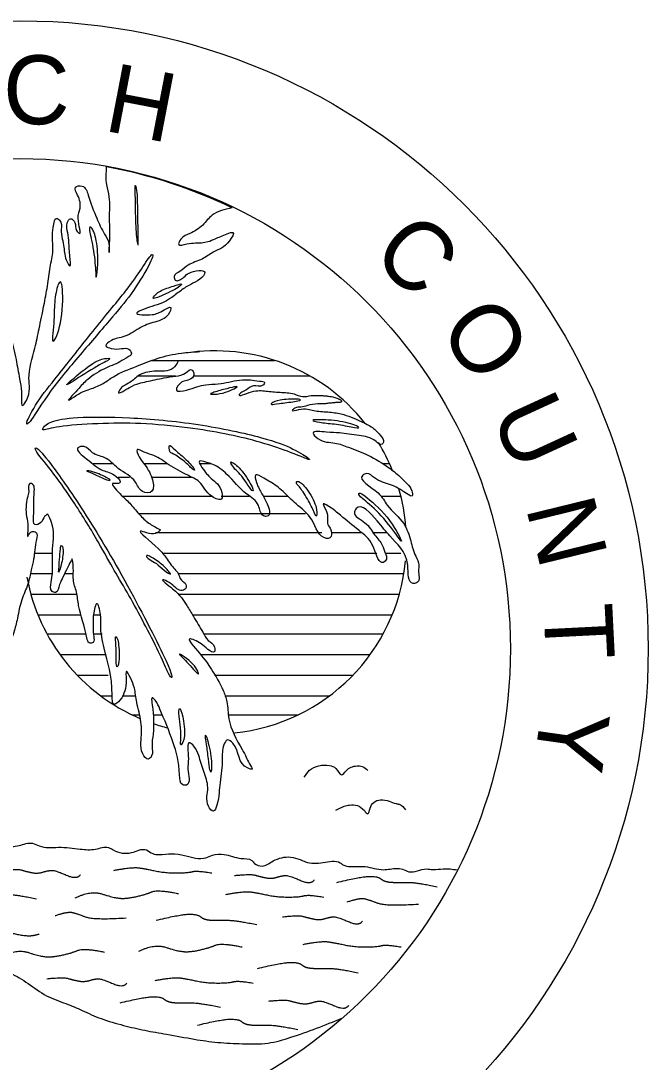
# Model space of a CAD drawing. Extents: x 801329 to 1085229, y 842463 to 1044570.
# Drawn here: x 938507 to 954829, y 915074 to 942158 of the extents above; entities that cross this region are included whole.
import ezdxf

# ---------------------------------------------------------------- set-up
doc = ezdxf.new("R2010")
doc.units = 0
doc.layers.add('Default', color=7, linetype='Continuous')

msp = doc.modelspace()

# ---------------------------------------------------------------- linework, layer by layer
at = {"layer": 'Default'}
for p, q in [((941919, 933328), (945109, 933328)), ((941564, 932925), (942530, 932925)), ((943012, 932925), (946020, 932925)), ((940388, 930643), (940893, 930643)), ((941726, 930643), (942313, 930643)), ((943146, 930643), (943460, 930643)), ((947923, 930643), (948100, 930643)), ((941043, 930286), (941330, 930286)), ((941917, 930286), (942949, 930286)), ((941166, 929793), (943487, 929793)), ((943722, 929793), (944447, 929793)), ((944835, 929793), (945451, 929793)), ((947889, 929793), (948394, 929793)), ((941576, 929346), (945915, 929346)), ((942013, 928854), (946337, 928854)), ((946590, 928854), (947366, 928854)), ((947653, 928854), (948041, 928854)), ((938868, 928317), (939323, 928317)), ((942217, 928317), (947771, 928317)), ((947990, 928317), (948395, 928317)), ((938757, 927780), (939316, 927780)), ((939644, 927780), (939869, 927780)), ((942613, 927780), (948474, 927780)), ((938768, 927243), (939965, 927243)), ((942600, 927243), (948354, 927243)), ((938953, 926706), (940074, 926706)), ((940395, 926706), (940565, 926706)), ((942974, 926706), (948169, 926706)), ((939187, 926214), (940197, 926214)), ((940401, 926214), (940622, 926214)), ((943283, 926214), (947935, 926214)), ((939525, 925678), (940702, 925678)), ((943191, 925678), (947597, 925678)), ((939973, 925141), (940782, 925141)), ((943545, 925141), (947148, 925141)), ((940582, 924604), (940873, 924604)), ((941147, 924604), (941501, 924604)), ((943819, 924604), (946539, 924604)), ((941392, 924112), (941593, 924112)), ((941958, 924112), (942186, 924112)), ((943899, 924112), (945729, 924112))]:
    msp.add_line(p, q, dxfattribs=at)
for radius in [16331, 12746]:
    msp.add_circle((938498, 925828), radius, dxfattribs=at)
for centre, radius, start, end in [((938456, 925819), 12746, 64.2352, 79.6894), ((943561, 928595), 4980, 38.42, 99.1431), ((943561, 928595), 4980, 22.2074, 31.4178), ((943561, 928595), 4980, 4.4987, 16.2458), ((943561, 928595), 4980, 275.8177, 354.498), ((943561, 928595), 4980, 190.4463, 247.1077), ((943561, 928595), 4980, 251.2399, 255.6912)]:
    msp.add_arc(centre, radius, start, end, dxfattribs=at)
for points in [[(934285, 935040), (934093, 935338), (933820, 935630), (933414, 935944), (933247, 936075), (933242, 936183), (933450, 936214), (933843, 936054), (934355, 935907), (934600, 935842), (934845, 935759), (934986, 935682), (935065, 935621), (935214, 935501), (935104, 935694), (934969, 935897), (934823, 936043), (934685, 936156), (934730, 936275), (934860, 936245), (935268, 936013), (935703, 935691), (936012, 935415), (936186, 935234), (936368, 935334), (936274, 935660), (936124, 935909), (936047, 936005), (935946, 936108), (936045, 936174), (936393, 935960), (936788, 935602), (937109, 935261), (937277, 935022), (937508, 934626), (937522, 934957), (937482, 935291), (937360, 935484), (937283, 935637), (937332, 935739), (937505, 935669), (937806, 935144), (938064, 934393), (938238, 933942), (938382, 933347), (938475, 932848), (938522, 932521), (938521, 932302), (938545, 932155), (938651, 932285), (938719, 932858), (938874, 933648), (938982, 934146), (939107, 934752), (939198, 935261), (939270, 935754), (939340, 936180), (939331, 936572), (939363, 936867), (939430, 937016), (939516, 936977), (939559, 936730), (939629, 936270), (939710, 935886), (939783, 935783), (939783, 936049), (939729, 936646), (939715, 936905), (939799, 937010), (939912, 936914), (939958, 936703), (940023, 936632), (939997, 937013), (940047, 937283), (939985, 937628), (939929, 937828), (940101, 937860), (940258, 937628), (940481, 937030), (940684, 936612), (940798, 936365), (940801, 936135), (940822, 936510), (940815, 937042), (940808, 937578), (940743, 937894), (940738, 938360)], [(944004, 937295), (943481, 937100), (943240, 936848), (942905, 936628), (942670, 936481), (942615, 936340), (942823, 936354), (943052, 936382), (943375, 936415), (943560, 936490), (943875, 936616), (944025, 936654), (943938, 936437), (943511, 936140), (943223, 935963), (942862, 935804), (942645, 935642), (942496, 935507), (942526, 935414), (942744, 935489), (942883, 935599), (943295, 935612), (943165, 935441), (942926, 935304), (942666, 935139), (942403, 934941), (942189, 934823), (941914, 934730), (941671, 934644), (941529, 934566), (941924, 934517), (942070, 934555), (942238, 934644), (942406, 934704), (942337, 934516), (942041, 934339), (941641, 934190), (941210, 933954), (941024, 933904), (940863, 933845), (940721, 933702), (940858, 933639), (941128, 933632), (941318, 933617), (941381, 933485), (941303, 933419), (941086, 933290), (940664, 933101), (940202, 932792), (939936, 932512), (939749, 932290), (939952, 932418), (940348, 932593), (940651, 932730), (940915, 932903), (941521, 933174), (942057, 933375), (942683, 933517), (943160, 933556)], [(942600, 933304), (942466, 933122), (941975, 933043), (941560, 932922), (941312, 932732), (941126, 932618), (941045, 932491), (941338, 932624), (941774, 932774), (942229, 932870), (942537, 932918), (942808, 933008), (942951, 933085), (942995, 933021), (943003, 932917), (942825, 932803), (942689, 932758), (942556, 932551), (942821, 932555), (943318, 932695), (943645, 932714), (943920, 932764), (944200, 932815), (944480, 932819), (944713, 932789), (944850, 932748), (944804, 932679), (944564, 932665), (944361, 932554), (944229, 932481), (944190, 932437), (944509, 932506), (944885, 932529), (945252, 932498), (945615, 932453), (945835, 932387), (946064, 932416)], [(946440, 932201), (946232, 932195), (945963, 932152), (945788, 932113), (945637, 932086), (945570, 932024), (945739, 932048), (946134, 932021), (946493, 931986), (946842, 931934), (947361, 931736), (947654, 931578), (947854, 931386), (947942, 931197), (947904, 931146), (947748, 931219), (947308, 931372), (946794, 931440), (946457, 931461), (946112, 931438), (946236, 931292), (946679, 931176), (947032, 931066), (947548, 930857), (948076, 930540), (948374, 930300), (948552, 930122), (948680, 929937), (948689, 929804), (948537, 929867), (948125, 930091), (947710, 930269), (947501, 930385), (947401, 930340), (947801, 929878), (948042, 929561), (948468, 929082), (948650, 928631), (948781, 928233), (948866, 928008), (948854, 927857), (948829, 927558), (948718, 927524), (948572, 928004), (948107, 928760), (947778, 929155), (947232, 929471), (947190, 929388), (947460, 929104), (947715, 928784), (947912, 928520), (947986, 928316), (948017, 928155), (947939, 928074), (947694, 928445), (947355, 928861), (946887, 929243), (946590, 929480), (946373, 929596), (946462, 929396), (946498, 929055), (946572, 928923), (946546, 928710), (946460, 928698), (946077, 929178), (945670, 929594), (945328, 929913), (944998, 930167), (944828, 930262), (944619, 930346), (944636, 930152), (944780, 929855), (944890, 929644), (944964, 929455), (944945, 929282), (944819, 929287), (944690, 929552), (944385, 929850), (943861, 930371), (943503, 930622), (943323, 930680), (943154, 930707), (943220, 930542), (943461, 930258), (943621, 930113), (943735, 929887), (943730, 929725), (943481, 929787), (943150, 930167), (942853, 930339), (942358, 930610)], [(946440, 932201), (946232, 932195), (945963, 932152), (945788, 932113), (945637, 932086), (945570, 932024), (945739, 932048), (946134, 932021), (946493, 931986), (946842, 931934), (947361, 931736), (947654, 931578), (947854, 931386), (947942, 931197), (947904, 931146), (947748, 931219), (947308, 931372), (946794, 931440), (946457, 931461), (946112, 931438), (946236, 931292), (946679, 931176), (947032, 931066), (947548, 930857), (948076, 930540), (948374, 930300), (948552, 930122), (948680, 929937), (948689, 929804), (948537, 929867), (948125, 930091), (947710, 930269), (947501, 930385), (947401, 930340), (947801, 929878), (948042, 929561), (948468, 929082), (948650, 928631), (948781, 928233), (948866, 928008), (948854, 927857), (948829, 927558), (948718, 927524), (948572, 928004), (948107, 928760), (947778, 929155), (947232, 929471), (947190, 929388), (947460, 929104), (947715, 928784), (947912, 928520), (947986, 928316), (948017, 928155), (947939, 928074), (947694, 928445), (947355, 928861), (946887, 929243), (946590, 929480), (946373, 929596), (946462, 929396), (946498, 929055), (946572, 928923), (946546, 928710), (946460, 928698), (946077, 929178), (945670, 929594), (945328, 929913), (944998, 930167), (944828, 930262), (944619, 930346), (944636, 930152), (944780, 929855), (944890, 929644), (944964, 929455), (944945, 929282), (944819, 929287), (944690, 929552), (944385, 929850), (943861, 930371), (943503, 930622), (943323, 930680), (943154, 930707), (943220, 930542), (943461, 930258), (943621, 930113), (943735, 929887), (943730, 929725), (943481, 929787), (943150, 930167), (942853, 930339), (942358, 930610)], [(942358, 930610), (941971, 930849), (941719, 930943), (941535, 931005), (941587, 930815), (941737, 930608), (941932, 930222), (941956, 930047), (941918, 929927), (941671, 929917), (941488, 930162), (941038, 930519), (940676, 930802), (940369, 930924), (940155, 931087), (939994, 931049), (940217, 930767), (940641, 930467), (940991, 930307), (941086, 930146), (940965, 930123), (940907, 930129), (941079, 929865), (941370, 929578), (941618, 929290), (941868, 929074), (942143, 928923)], [(942358, 930610), (941971, 930849), (941719, 930943), (941535, 931005), (941587, 930815), (941737, 930608), (941932, 930222), (941956, 930047), (941918, 929927), (941671, 929917), (941488, 930162), (941038, 930519), (940676, 930802), (940369, 930924), (940155, 931087), (939994, 931049), (940217, 930767), (940641, 930467), (940991, 930307), (941086, 930146), (940965, 930123), (940907, 930129), (941079, 929865), (941370, 929578), (941618, 929290), (941868, 929074), (942143, 928923)], [(939209, 929329), (939127, 929267), (939029, 929111), (938868, 929055), (938840, 929274), (938851, 929828), (938783, 930122), (938743, 930121), (938713, 929919), (938679, 929764), (938657, 929267), (938693, 928977), (938689, 928746), (938766, 928862), (938906, 928850), (938912, 928670), (938840, 928159), (938779, 927877), (938690, 927509), (938531, 927100), (938418, 926620), (938323, 926248), (938177, 925869), (937979, 925323), (937859, 924925), (937680, 924322), (937506, 923867), (937264, 923450), (937039, 923054), (936856, 922786), (936799, 922497), (936733, 922338), (936221, 921903), (935730, 921299), (935295, 920797), (935029, 920527), (934728, 920239), (934600, 919899), (934443, 919515), (934391, 919122), (934430, 918839), (933627, 919026), (933318, 919072), (932919, 919138), (932567, 919166), (932358, 919185), (932337, 919197)], [(939845, 928165), (939726, 927948), (939603, 927687), (939516, 927499), (939411, 927292), (939321, 927320), (939300, 927560), (939332, 928428), (939360, 928781), (939309, 929107), (939209, 929329)], [(939845, 928165), (939726, 927948), (939603, 927687), (939516, 927499), (939411, 927292), (939321, 927320), (939300, 927560), (939332, 928428), (939360, 928781), (939309, 929107), (939209, 929329)], [(942143, 928923), (942011, 928821), (941623, 928887), (942081, 928433), (942289, 928191), (942511, 927896), (942588, 927807), (942687, 927607), (942782, 927529), (942791, 927389), (942669, 927340), (942539, 927411), (942369, 927548), (942195, 927622), (942457, 927384), (942825, 926954), (942997, 926668), (943122, 926454), (943243, 926255), (943382, 926044), (943549, 925870), (943540, 925744), (943374, 925810), (943197, 925955), (942901, 926085), (943153, 925710), (943467, 925290), (943769, 924744), (943866, 924450), (943918, 924008), (944266, 923204), (944372, 923004), (944457, 922836), (944523, 922696), (944423, 922717), (944019, 923373), (943882, 923454), (943790, 923330), (943749, 922949), (943695, 922351), (943663, 922080), (943610, 921763), (943518, 921600), (943391, 921731), (943370, 922217), (943268, 922633), (943134, 923052), (943005, 923294), (942900, 923383), (942865, 922969), (942855, 922695), (942813, 922281), (942720, 922287), (942637, 922545), (942465, 923402), (942127, 924257), (942002, 924486), (941937, 924553), (941941, 924258), (941960, 923910), (941949, 923614), (941921, 923287), (941910, 923038), (941828, 922958), (941679, 923093), (941633, 923387), (941633, 923927), (941522, 924432), (941460, 924806), (941356, 925070), (941253, 925242), (941249, 925026), (941210, 924734), (941084, 924488), (940931, 924381), (940885, 924614), (940675, 925842), (940585, 926449), (940581, 926715), (940477, 926997), (940421, 926856), (940386, 926511), (940402, 926147), (940386, 925993), (940289, 925980), (940227, 926109), (940011, 926951), (939953, 927303), (939873, 927622), (939874, 927849), (939845, 928165)], [(942143, 928923), (942011, 928821), (941623, 928887), (942081, 928433), (942289, 928191), (942511, 927896), (942588, 927807), (942687, 927607), (942782, 927529), (942791, 927389), (942669, 927340), (942539, 927411), (942369, 927548), (942195, 927622), (942457, 927384), (942825, 926954), (942997, 926668), (943122, 926454), (943243, 926255), (943382, 926044), (943549, 925870), (943540, 925744), (943374, 925810), (943197, 925955), (942901, 926085), (943153, 925710), (943467, 925290), (943769, 924744), (943866, 924450), (943918, 924008), (944266, 923204), (944372, 923004), (944457, 922836), (944523, 922696), (944423, 922717), (944019, 923373), (943882, 923454), (943790, 923330), (943749, 922949), (943695, 922351), (943663, 922080), (943610, 921763), (943518, 921600), (943391, 921731), (943370, 922217), (943268, 922633), (943134, 923052), (943005, 923294), (942900, 923383), (942865, 922969), (942855, 922695), (942813, 922281), (942720, 922287), (942637, 922545), (942465, 923402), (942127, 924257), (942002, 924486), (941937, 924553), (941941, 924258), (941960, 923910), (941949, 923614), (941921, 923287), (941910, 923038), (941828, 922958), (941679, 923093), (941633, 923387), (941633, 923927), (941522, 924432), (941460, 924806), (941356, 925070), (941253, 925242), (941249, 925026), (941210, 924734), (941084, 924488), (940931, 924381), (940885, 924614), (940675, 925842), (940585, 926449), (940581, 926715), (940477, 926997), (940421, 926856), (940386, 926511), (940402, 926147), (940386, 925993), (940289, 925980), (940227, 926109), (940011, 926951), (939953, 927303), (939873, 927622), (939874, 927849), (939845, 928165)], [(926047, 923062), (926568, 922940), (926962, 922729), (927346, 922454), (927604, 922220), (927887, 921954), (928127, 921659), (928379, 921360), (928624, 921047), (928850, 920734), (929467, 920170), (929859, 919830), (930460, 919479), (930974, 919261), (931311, 919225), (931711, 919270), (931992, 919216), (932594, 919161), (933577, 919052), (934177, 918770), (934963, 918709), (935445, 918604), (936195, 918338), (936993, 917982), (937593, 917684), (938228, 917394), (938698, 917120), (939172, 916803), (939681, 916598), (940107, 916420), (940594, 916207), (941181, 916032), (941729, 915903), (942301, 915802), (943020, 915672), (943628, 915590), (944271, 915553), (944938, 915572), (945535, 915721), (946859, 916216)], [(945879, 922485), (946020, 922667), (946263, 922785), (946536, 922789), (946702, 922712), (946847, 922545), (946972, 922654), (947100, 922746), (947254, 922781), (947387, 922768), (947535, 922662)], [(946705, 921629), (946919, 921729), (947059, 921760), (947263, 921748), (947444, 921618), (947535, 921536), (947594, 921677), (947689, 921830), (947868, 921901), (948087, 921860), (948271, 921798), (948354, 921781), (948517, 921640)], [(935360, 920835), (935769, 920818), (935956, 920730), (936060, 920775), (936251, 920869), (936371, 920873), (936602, 920739), (936767, 920763), (937028, 920835), (937295, 920759), (937486, 920712), (937729, 920805), (937937, 920736), (938261, 920683), (938465, 920711), (938813, 920769), (938986, 920700), (939485, 920663), (940053, 920617), (940448, 920615), (940788, 920655), (940911, 920593), (941386, 920524), (941579, 920591), (941776, 920594), (941939, 920499), (942104, 920473), (942434, 920495), (942769, 920446), (943322, 920392), (943490, 920459), (943795, 920478), (944234, 920376), (944514, 920319), (944587, 920244), (944786, 920175), (945075, 920308), (945525, 920408), (945774, 920343), (945911, 920287), (946371, 920269), (946816, 920260), (946888, 920211), (947086, 920163), (947463, 920161), (947941, 920081), (948117, 920098), (948440, 920092), (948603, 920029), (949057, 920100), (949230, 920085), (949492, 920103), (949858, 920077)]]:
    msp.add_spline(points, degree=3, dxfattribs=at)
for points, degree in [([(941562, 936370), (941558, 936289), (941527, 936350), (941481, 936952), (941481, 937716), (941457, 937901), (941550, 937855), (941550, 936837), (941566, 936451), (941562, 936370)], 3), ([(940473, 935513), (940462, 935471), (940462, 935517), (940416, 936188), (940254, 936813), (940346, 936813), (940485, 936512), (940531, 935772), (940485, 935556), (940473, 935513)], 3), ([(938675, 931751), (938633, 931636), (938725, 931651), (939211, 932485), (940114, 933549), (940948, 934522), (941434, 935100), (941944, 935957), (941967, 936188), (941643, 935702), (941319, 935216), (940462, 934197), (939489, 932947), (938980, 932346), (938718, 931867), (938675, 931751)], 3), ([(939335, 933974), (939343, 934074), (939374, 934290), (939374, 934846), (939466, 935355), (939605, 935448), (939605, 934336), (939327, 933688), (939327, 933873), (939335, 933974)], 3), ([(941959, 934969), (941936, 934931), (941967, 934915), (942592, 935193), (942754, 935355), (942500, 935262), (942106, 935147), (941982, 935008), (941959, 934969)], 3), ([(939783, 932774), (939667, 932670), (939698, 932670), (940462, 933179), (940925, 933387), (940693, 933387), (940392, 933295), (939898, 932878), (939783, 932774)], 3), ([(943495, 932446), (943434, 932446), (943403, 932461), (943796, 932577), (944097, 932647), (944167, 932647), (944028, 932577), (943773, 932461), (943557, 932446), (943495, 932446)], 3), ([(945035, 932180), (945008, 932183), (945024, 932230), (945301, 932323), (945903, 932323), (945672, 932253), (945186, 932207), (945062, 932176), (945035, 932180)], 3), ([(946064, 932416), (946487, 932421), (946836, 932313), (946863, 932233), (946702, 932233), (946434, 932201)], 2), ([(939096, 931578), (939065, 931535), (939049, 931489), (939489, 931628), (940670, 931697), (941735, 931697), (943055, 931559), (943935, 931397), (944746, 931211), (945602, 930910), (945973, 930748), (946089, 930725), (945626, 931026), (944931, 931304), (943125, 931697), (941272, 931859), (939860, 931859), (939235, 931744), (939127, 931620), (939096, 931578)], 3), ([(946112, 931759), (946081, 931775), (946158, 931790), (946830, 931767), (947385, 931582), (947246, 931559), (946760, 931674), (946343, 931697), (946143, 931744), (946112, 931759)], 3), ([(938933, 931034), (938871, 931077), (938822, 931040), (939377, 930375), (939876, 929672), (940579, 928525), (940931, 927859), (941319, 927230), (941708, 926509), (942115, 925714), (942337, 925196), (942429, 925029), (942485, 925159), (941282, 927526), (940098, 929505), (939192, 930781), (938994, 930991), (938933, 931034)], 3), ([(942384, 930960), (942399, 930918), (942430, 930934), (942777, 930702), (942986, 930471), (943078, 930447), (942824, 930748), (942500, 931003), (942338, 931188), (942368, 931003), (942384, 930960)], 3), ([(943978, 930640), (943997, 930602), (944074, 930494), (944213, 930378), (944375, 930147), (944537, 929892), (944584, 929961), (944259, 930494), (943958, 930725), (943958, 930679), (943978, 930640)], 3), ([(940228, 930445), (940211, 930455), (940242, 930471), (940497, 930389), (940670, 930320), (940902, 930193), (940705, 930216), (940346, 930413), (940246, 930436), (940228, 930445)], 3), ([(945680, 930123), (945687, 930100), (945718, 930100), (945973, 929730), (946158, 929336), (946205, 929221), (946228, 929498), (945950, 930031), (945672, 930239), (945672, 930146), (945680, 930123)], 3), ([(947300, 929861), (947297, 929838), (947328, 929776), (947814, 929406), (948346, 928711), (948485, 928503), (948092, 929267), (947351, 929915), (947304, 929884), (947300, 929861)], 3), ([(939559, 928513), (939543, 928513), (939543, 928451), (939506, 928137), (939506, 927878), (939469, 927767), (939562, 927970), (939636, 928451), (939574, 928513), (939559, 928513)], 3), ([(941779, 928220), (941763, 928248), (941800, 928284), (942170, 928044), (942374, 927822), (942429, 927748), (942300, 927804), (942078, 928026), (941893, 928118), (941794, 928192), (941779, 928220)], 3), ([(941045, 925970), (941023, 926102), (940949, 926213), (940986, 925917), (940986, 925603), (940986, 925288), (941079, 925418), (941066, 925837), (941045, 925970)], 3), ([(942648, 925664), (942627, 925689), (942614, 925714), (942892, 925529), (943077, 925325), (943151, 925159), (943095, 925177), (942910, 925399), (942744, 925566), (942670, 925640), (942648, 925664)], 3), ([(942633, 924274), (942614, 924265), (942614, 924067), (942670, 923790), (942670, 923402), (942651, 923272), (942799, 923494), (942725, 924123), (942651, 924283), (942633, 924274)], 3), ([(943308, 923537), (943311, 923494), (943336, 923383), (943391, 922939), (943428, 922643), (943465, 922569), (943484, 922995), (943317, 923642), (943305, 923580), (943308, 923537)], 3), ([(937977, 920063), (938402, 920108), (938626, 920040), (938939, 919973), (939230, 920063), (939409, 920063), (939968, 919817), (940058, 919951)], 2), ([(940930, 920063), (941400, 920152), (941735, 920108), (942250, 919996), (942854, 919996), (943077, 920063), (943480, 919996)], 2), ([(944062, 919929), (944487, 919973), (944710, 919906), (945024, 919839), (945314, 919929), (945493, 919929), (946052, 919683), (946142, 919817)], 2), ([(946724, 919750), (947372, 919906), (947797, 919906), (947931, 919794), (948110, 919750), (948423, 919750), (948781, 919750), (949341, 919638)], 2), ([(936300, 919437), (936949, 919593), (937374, 919593), (937508, 919481), (937687, 919437), (938000, 919437), (938358, 919437), (938917, 919325)], 2), ([(939924, 919347), (940326, 919548), (940930, 919347), (941266, 919325), (941758, 919437), (942071, 919571), (942608, 919459)], 2), ([(943838, 919437), (944308, 919526), (944643, 919481), (945158, 919369), (945762, 919369), (945985, 919437), (946388, 919369)], 2), ([(947001, 919243), (947338, 919355), (947562, 919299), (948011, 919130), (948853, 919186)], 2), ([(939396, 918885), (939733, 918997), (939957, 918941), (940406, 918772), (941248, 918828)], 2), ([(942026, 918765), (942675, 918922), (943100, 918922), (943234, 918810), (943413, 918765), (943726, 918765), (944084, 918765), (944643, 918654)], 2), ([(945314, 918855), (945739, 918900), (945963, 918833), (946276, 918765), (946567, 918855), (946746, 918855), (947305, 918609), (947395, 918743)], 2), ([(936277, 918542), (936814, 918564), (936926, 918452), (937306, 918385), (937396, 918408), (937888, 918542), (938335, 918408), (938783, 918340), (938984, 918408)], 2), ([(945851, 918139), (946321, 918229), (946656, 918184), (947171, 918072), (947775, 918072), (947999, 918139), (948401, 918072)], 2), ([(938000, 917826), (938402, 918027), (939006, 917826), (939342, 917804), (939834, 917915), (940147, 918049), (940684, 917938)], 2), ([(941579, 917960), (941981, 918161), (942585, 917960), (942921, 917938), (943413, 918049), (943726, 918184), (944263, 918072)], 2), ([(944666, 917513), (945314, 917669), (945739, 917669), (945874, 917557), (946052, 917513), (946366, 917513), (946724, 917513), (947283, 917401)], 2), ([(939185, 917244), (939610, 917289), (939834, 917222), (940147, 917155), (940438, 917244), (940617, 917244), (941176, 916998), (941266, 917133)], 2), ([(942004, 917200), (942474, 917289), (942809, 917244), (943324, 917133), (943928, 917133), (944151, 917200), (944554, 917133)], 2), ([(941087, 916618), (941735, 916775), (942160, 916775), (942295, 916663), (942474, 916618), (942787, 916618), (943145, 916618), (943704, 916506)], 2), ([(944956, 916663), (945381, 916707), (945605, 916640), (945918, 916573), (946209, 916663), (946388, 916663), (946947, 916417), (947037, 916551)], 2), ([(943100, 916036), (943749, 916193), (944174, 916193), (944308, 916081), (944487, 916036), (944800, 916036), (945158, 916036), (945717, 915925)], 2)]:
    msp.add_open_spline(points, degree=degree, dxfattribs=at)

# ---------------------------------------------------------------- texts
for s, rotation, p in [('C', 0.0002, (938046, 939469)), ('H', 349.1091, (940632, 939309)), ('C', 316.4358, (947572, 936024)), ('O', 305.5448, (949335, 934126)), ('U', 294.6537, (950711, 931922)), ('N', 283.7626, (951641, 929512)), ('T', 272.8715, (952100, 926955)), ('Y', 261.9804, (952068, 924364))]:
    msp.add_text(s, height=1792, rotation=rotation, dxfattribs=at).set_placement(p)

doc.saveas('drawing.dxf')
